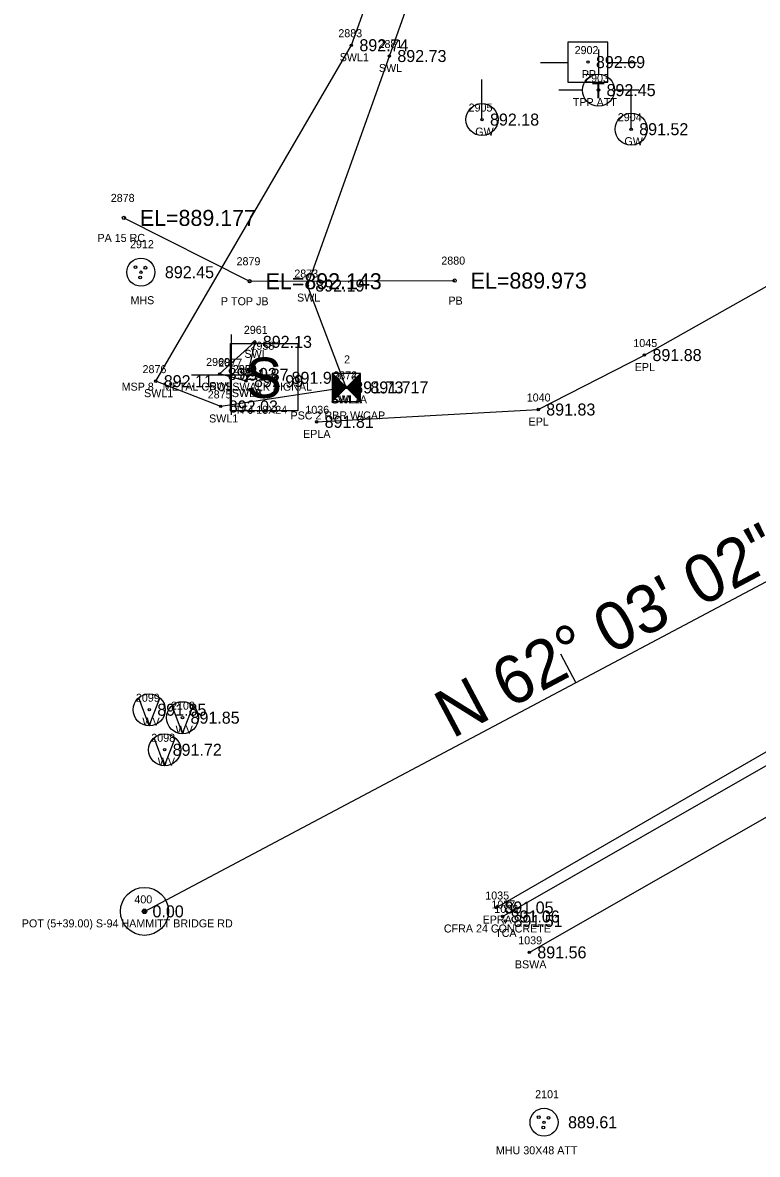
# Model space of a CAD drawing. Extents: x 1622501 to 1626664, y 1117816 to 1121579.
# Drawn here: x 1623223.8 to 1623315.6, y 1118634.5 to 1118775.8 of the extents above; entities that cross this region are included whole.
import ezdxf

# ---------------------------------------------------------------- set-up
doc = ezdxf.new("R2010")
doc.units = 0
for name, color, linetype in [('RD_EX_Conc', 7, 'Continuous'), ('RD_EX_Conc_txCode', 7, 'Continuous'), ('RD_EX_DR_Inlet', 7, 'Continuous'), ('RD_EX_DR_Pipe', 7, 'Continuous'), ('RD_EX_DR_Pipe_txCode', 7, 'Continuous'), ('RD_EX_DV_Prop_txCode', 7, 'Continuous'), ('RD_EX_Misc', 7, 'Continuous'), ('RD_EX_Misc_txCode', 7, 'Continuous'), ('RD_EX_Road', 7, 'Continuous'), ('RD_EX_Road_txCode', 7, 'Continuous'), ('RD_EX_TX_Conc_ELEV', 7, 'Continuous'), ('RD_EX_TX_Misc_ELEV', 7, 'Continuous'), ('RD_EX_TX_Road_ELEV', 7, 'Continuous'), ('RD_EX_TX_UT_ELEV', 7, 'Continuous'), ('RD_EX_UT', 7, 'Continuous'), ('RD_EX_UT_txCode', 7, 'Continuous'), ('RD_HC_Cl', 7, 'Continuous'), ('RD_HC_Data', 7, 'Continuous'), ('RD_HC_Data_Tic', 7, 'Continuous'), ('RD_HC_Survey', 7, 'Continuous'), ('RD_HC_Survey_ELEV', 7, 'Continuous'), ('RD_HC_txCode', 7, 'Continuous'), ('RD_SMD_Locator', 7, 'Continuous'), ('RD_TX_Pipe_ElevEX', 7, 'Continuous')]:
    doc.layers.add(name, color=color, linetype=linetype)

msp = doc.modelspace()

# ---------------------------------------------------------------- linework, layer by layer
at = {"layer": 'RD_EX_Conc'}
for points in [[(1623283.76, 1118664.17), (1623326.75, 1118688.79), (1623370.21, 1118712.76), (1623413.97, 1118736.47), (1623457.08, 1118761.62), (1623498.83, 1118789.05), (1623539.22, 1118818.4), (1623578.61, 1118849.25), (1623610.29, 1118876.06), (1623617.2, 1118880.67), (1623627.78, 1118883.82), (1623633.91, 1118884.57), (1623640.77, 1118884.03), (1623649.39, 1118881.53), (1623657, 1118877.66), (1623663.67, 1118871.91), (1623688.62, 1118845.06), (1623694.12, 1118836.37)], [(1623287.1, 1118659.69), (1623329.45, 1118683.88), (1623372.88, 1118707.9), (1623416.57, 1118731.52), (1623459.84, 1118756.85), (1623502.1, 1118784.62), (1623542.54, 1118813.86), (1623581.97, 1118844.89), (1623613.89, 1118871.89), (1623619.42, 1118875.42), (1623623.69, 1118876.74), (1623623.46, 1118877.27), (1623631.27, 1118878.69), (1623634.06, 1118878.85), (1623639.63, 1118878.45), (1623640.56, 1118883.37)], [(1623264.24, 1118730.25), (1623248.57, 1118727.87), (1623240.45, 1118731.03), (1623264.88, 1118772.99), (1623273.59, 1118797.21)], [(1623264.24, 1118730.25), (1623259.38, 1118742.97), (1623269.62, 1118771.64), (1623278.13, 1118795.56)], [(1623251.72, 1118731.04), (1623248.43, 1118731.93), (1623252.82, 1118735.94), (1623251.72, 1118731.04)]]:
    msp.add_lwpolyline(points, dxfattribs=at)
at = {"layer": 'RD_EX_DR_Inlet'}
for centre, radius in [((1623238.59, 1118744.64), 1.75), ((1623237.92, 1118745.27), 0.175), ((1623239.15, 1118745.2), 0.175), ((1623238.5, 1118743.98), 0.175), ((1623288.94, 1118638.47), 1.75), ((1623288.27, 1118639.1), 0.175), ((1623289.5, 1118639.03), 0.175), ((1623288.85, 1118637.81), 0.175)]:
    msp.add_circle(centre, radius, dxfattribs=at)
at = {"layer": 'RD_EX_DR_Pipe'}
msp.add_lwpolyline([(1623236.46, 1118751.42), (1623252.17, 1118743.51), (1623277.78, 1118743.59)], dxfattribs=at)
at = {"layer": 'RD_EX_DV_Prop_txCode'}
msp.add_lwpolyline([(1623249.79, 1118727.33), (1623249.79, 1118735.73), (1623258.19, 1118735.73), (1623258.19, 1118727.33)], close=True, dxfattribs=at)
at = {"layer": 'RD_EX_Misc'}
for p, q in [((1623249.9, 1118726.84), (1623249.9, 1118736.84)), ((1623244.9, 1118731.84), (1623254.9, 1118731.84))]:
    msp.add_line(p, q, dxfattribs=at)
at = {"layer": 'RD_EX_Road'}
for points in [[(1623260.54, 1118725.95), (1623288.21, 1118727.49), (1623301.48, 1118734.29), (1623344.73, 1118758.67), (1623386.19, 1118782.36), (1623428.98, 1118807.99), (1623470.08, 1118833.28), (1623514.57, 1118855.09), (1623531.48, 1118864.83), (1623546.9, 1118877), (1623552.55, 1118884.26), (1623552.91, 1118883.94), (1623553.83, 1118883.16), (1623571.54, 1118911.83), (1623572.65, 1118913.7), (1623580.36, 1118928.72), (1623584.23, 1118943.72), (1623583.03, 1118956.88), (1623577.5, 1118968.65), (1623574.75, 1118973.14), (1623569.43, 1118983.78), (1623564.78, 1119000.82), (1623565.61, 1119022.95), (1623574.2, 1119045.06)], [(1623282.99, 1118665.29), (1623326.11, 1118690.17), (1623369.47, 1118714.08), (1623413.31, 1118737.63), (1623456.35, 1118762.8), (1623498.01, 1118790.21), (1623538.41, 1118819.48), (1623577.72, 1118850.34), (1623609.41, 1118877.29), (1623616.69, 1118881.9), (1623627.61, 1118885.26), (1623634.06, 1118885.78), (1623640.82, 1118885.36), (1623649.78, 1118882.4), (1623657.44, 1118878.35), (1623664.36, 1118872.55), (1623689.27, 1118845.67), (1623694.99, 1118836.79)]]:
    msp.add_lwpolyline(points, dxfattribs=at)
at = {"layer": 'RD_EX_UT'}
for p, q in [((1623296.92, 1118773.39), (1623291.92, 1118773.39)), ((1623291.92, 1118773.39), (1623291.92, 1118768.39)), ((1623296.92, 1118768.39), (1623296.92, 1118773.39)), ((1623295.74, 1118772.45), (1623295.74, 1118769.38)), ((1623288.48, 1118770.83), (1623291.95, 1118770.83)), ((1623296.84, 1118770.83), (1623300.48, 1118770.83)), ((1623281.19, 1118763.7), (1623281.19, 1118768.7)), ((1623290.8, 1118767.4), (1623293.74, 1118767.4)), ((1623291.92, 1118768.39), (1623296.92, 1118768.39)), ((1623297.74, 1118767.4), (1623300.8, 1118767.4)), ((1623299.82, 1118762.5), (1623299.82, 1118767.5)), ((1623239.64, 1118687.99), (1623238.33, 1118691.48)), ((1623239.64, 1118687.99), (1623240.96, 1118691.44)), ((1623243.79, 1118687.01), (1623242.49, 1118690.49)), ((1623243.79, 1118687.01), (1623245.11, 1118690.46)), ((1623241.56, 1118682.99), (1623240.26, 1118686.48)), ((1623241.56, 1118682.99), (1623242.88, 1118686.44))]:
    msp.add_line(p, q, dxfattribs=at)
for centre in [(1623295.74, 1118767.38), (1623281.19, 1118763.7), (1623299.82, 1118762.5), (1623239.64, 1118689.99), (1623243.79, 1118689), (1623241.56, 1118684.99)]:
    msp.add_circle(centre, 2, dxfattribs=at)
at = {"layer": 'RD_HC_Cl'}
msp.add_line((1623239.04, 1118664.81), (1623369.72, 1118734.14), dxfattribs=at)
at = {"layer": 'RD_HC_Data'}
for radius in [3, 0.282]:
    msp.add_circle((1623239.04, 1118664.81), radius, dxfattribs=at)
at = {"layer": 'RD_HC_Data_Tic'}
msp.add_line((1623292.92, 1118693.4), (1623291.05, 1118696.93), dxfattribs=at)
at = {"layer": 'RD_HC_Survey'}
for p, q in [((1623262.5, 1118732), (1623266, 1118728.5)), ((1623266, 1118732), (1623262.5, 1118728.5)), ((1623262.52, 1118731.98), (1623262.52, 1118728.52)), ((1623262.55, 1118731.95), (1623262.55, 1118728.55)), ((1623265.95, 1118731.95), (1623265.95, 1118728.55)), ((1623265.98, 1118731.98), (1623265.98, 1118728.52)), ((1623262.57, 1118731.93), (1623262.57, 1118728.57)), ((1623262.6, 1118731.9), (1623262.6, 1118728.6)), ((1623262.62, 1118731.88), (1623262.62, 1118728.62)), ((1623262.65, 1118731.85), (1623262.65, 1118728.65)), ((1623262.67, 1118731.83), (1623262.67, 1118728.67)), ((1623262.7, 1118731.8), (1623262.7, 1118728.7)), ((1623262.72, 1118731.78), (1623262.72, 1118728.72)), ((1623262.75, 1118731.75), (1623262.75, 1118728.75)), ((1623262.77, 1118731.73), (1623262.77, 1118728.77)), ((1623262.8, 1118731.7), (1623262.8, 1118728.8)), ((1623262.82, 1118731.68), (1623262.82, 1118728.82)), ((1623262.85, 1118731.65), (1623262.85, 1118728.85)), ((1623262.87, 1118731.63), (1623262.87, 1118728.87)), ((1623262.9, 1118731.6), (1623262.9, 1118728.9)), ((1623262.92, 1118731.58), (1623262.92, 1118728.92)), ((1623262.95, 1118731.55), (1623262.95, 1118728.95)), ((1623262.97, 1118731.53), (1623262.97, 1118728.97)), ((1623262.99, 1118731.51), (1623262.99, 1118728.99)), ((1623263.02, 1118731.48), (1623263.02, 1118729.02)), ((1623263.04, 1118731.46), (1623263.04, 1118729.04)), ((1623263.07, 1118731.43), (1623263.07, 1118729.07)), ((1623263.09, 1118731.41), (1623263.09, 1118729.09)), ((1623263.12, 1118731.38), (1623263.12, 1118729.12)), ((1623263.14, 1118731.36), (1623263.14, 1118729.14)), ((1623263.17, 1118731.33), (1623263.17, 1118729.17)), ((1623263.19, 1118731.31), (1623263.19, 1118729.19)), ((1623263.22, 1118731.28), (1623263.22, 1118729.22)), ((1623263.24, 1118731.26), (1623263.24, 1118729.24)), ((1623263.27, 1118731.23), (1623263.27, 1118729.27)), ((1623263.29, 1118731.21), (1623263.29, 1118729.29)), ((1623263.32, 1118731.18), (1623263.32, 1118729.32)), ((1623263.34, 1118731.16), (1623263.34, 1118729.34)), ((1623263.37, 1118731.13), (1623263.37, 1118729.37)), ((1623263.39, 1118731.11), (1623263.39, 1118729.39)), ((1623263.42, 1118731.08), (1623263.42, 1118729.42)), ((1623263.44, 1118731.06), (1623263.44, 1118729.44)), ((1623263.47, 1118731.03), (1623263.47, 1118729.47)), ((1623263.49, 1118731.01), (1623263.49, 1118729.49)), ((1623263.51, 1118730.99), (1623263.51, 1118729.51)), ((1623263.54, 1118730.96), (1623263.54, 1118729.54)), ((1623263.56, 1118730.94), (1623263.56, 1118729.56)), ((1623263.59, 1118730.91), (1623263.59, 1118729.59)), ((1623263.61, 1118730.89), (1623263.61, 1118729.61)), ((1623263.64, 1118730.86), (1623263.64, 1118729.64)), ((1623263.66, 1118730.84), (1623263.66, 1118729.66)), ((1623263.69, 1118730.81), (1623263.69, 1118729.69)), ((1623263.71, 1118730.79), (1623263.71, 1118729.71)), ((1623263.74, 1118730.76), (1623263.74, 1118729.74)), ((1623263.76, 1118730.74), (1623263.76, 1118729.76)), ((1623263.79, 1118730.71), (1623263.79, 1118729.79)), ((1623263.81, 1118730.69), (1623263.81, 1118729.81)), ((1623263.84, 1118730.66), (1623263.84, 1118729.84)), ((1623263.86, 1118730.64), (1623263.86, 1118729.86)), ((1623263.89, 1118730.61), (1623263.89, 1118729.89)), ((1623263.91, 1118730.59), (1623263.91, 1118729.91)), ((1623263.94, 1118730.56), (1623263.94, 1118729.94)), ((1623263.96, 1118730.54), (1623263.96, 1118729.96)), ((1623264.54, 1118730.54), (1623264.54, 1118729.96)), ((1623264.56, 1118730.56), (1623264.56, 1118729.94)), ((1623264.59, 1118730.59), (1623264.59, 1118729.91)), ((1623264.61, 1118730.61), (1623264.61, 1118729.89)), ((1623264.64, 1118730.64), (1623264.64, 1118729.86)), ((1623264.66, 1118730.66), (1623264.66, 1118729.84)), ((1623264.69, 1118730.69), (1623264.69, 1118729.81)), ((1623264.71, 1118730.71), (1623264.71, 1118729.79)), ((1623264.74, 1118730.74), (1623264.74, 1118729.76)), ((1623264.76, 1118730.76), (1623264.76, 1118729.74)), ((1623264.79, 1118730.79), (1623264.79, 1118729.71)), ((1623264.81, 1118730.81), (1623264.81, 1118729.69)), ((1623264.84, 1118730.84), (1623264.84, 1118729.66)), ((1623264.86, 1118730.86), (1623264.86, 1118729.64)), ((1623264.89, 1118730.89), (1623264.89, 1118729.61)), ((1623264.91, 1118730.91), (1623264.91, 1118729.59)), ((1623264.94, 1118730.94), (1623264.94, 1118729.56)), ((1623264.96, 1118730.96), (1623264.96, 1118729.54)), ((1623264.99, 1118730.99), (1623264.99, 1118729.51)), ((1623265.01, 1118731.01), (1623265.01, 1118729.49)), ((1623265.03, 1118731.03), (1623265.03, 1118729.47)), ((1623265.06, 1118731.06), (1623265.06, 1118729.44)), ((1623265.08, 1118731.08), (1623265.08, 1118729.42)), ((1623265.11, 1118731.11), (1623265.11, 1118729.39)), ((1623265.13, 1118731.13), (1623265.13, 1118729.37)), ((1623265.16, 1118731.16), (1623265.16, 1118729.34)), ((1623265.18, 1118731.18), (1623265.18, 1118729.32)), ((1623265.21, 1118731.21), (1623265.21, 1118729.29)), ((1623265.23, 1118731.23), (1623265.23, 1118729.27)), ((1623265.26, 1118731.26), (1623265.26, 1118729.24)), ((1623265.28, 1118731.28), (1623265.28, 1118729.22)), ((1623265.31, 1118731.31), (1623265.31, 1118729.19)), ((1623265.33, 1118731.33), (1623265.33, 1118729.17)), ((1623265.36, 1118731.36), (1623265.36, 1118729.14)), ((1623265.38, 1118731.38), (1623265.38, 1118729.12)), ((1623265.41, 1118731.41), (1623265.41, 1118729.09)), ((1623265.43, 1118731.43), (1623265.43, 1118729.07)), ((1623265.46, 1118731.46), (1623265.46, 1118729.04)), ((1623265.48, 1118731.48), (1623265.48, 1118729.02)), ((1623265.51, 1118731.51), (1623265.51, 1118728.99)), ((1623265.53, 1118731.53), (1623265.53, 1118728.97)), ((1623265.55, 1118731.55), (1623265.55, 1118728.95)), ((1623265.58, 1118731.58), (1623265.58, 1118728.92)), ((1623265.6, 1118731.6), (1623265.6, 1118728.9)), ((1623265.63, 1118731.63), (1623265.63, 1118728.87)), ((1623265.65, 1118731.65), (1623265.65, 1118728.85)), ((1623265.68, 1118731.68), (1623265.68, 1118728.82)), ((1623265.7, 1118731.7), (1623265.7, 1118728.8)), ((1623265.73, 1118731.73), (1623265.73, 1118728.77)), ((1623265.75, 1118731.75), (1623265.75, 1118728.75)), ((1623265.78, 1118731.78), (1623265.78, 1118728.72)), ((1623265.8, 1118731.8), (1623265.8, 1118728.7)), ((1623265.83, 1118731.83), (1623265.83, 1118728.67)), ((1623265.85, 1118731.85), (1623265.85, 1118728.65)), ((1623265.88, 1118731.88), (1623265.88, 1118728.62)), ((1623265.9, 1118731.9), (1623265.9, 1118728.6)), ((1623265.93, 1118731.93), (1623265.93, 1118728.57)), ((1623263.98, 1118730.52), (1623263.98, 1118729.98)), ((1623264.01, 1118730.49), (1623264.01, 1118730.01)), ((1623264.03, 1118730.47), (1623264.03, 1118730.03)), ((1623264.06, 1118730.44), (1623264.06, 1118730.06)), ((1623264.08, 1118730.42), (1623264.08, 1118730.08)), ((1623264.11, 1118730.39), (1623264.11, 1118730.11)), ((1623264.13, 1118730.37), (1623264.13, 1118730.13)), ((1623264.16, 1118730.34), (1623264.16, 1118730.16)), ((1623264.18, 1118730.32), (1623264.18, 1118730.18)), ((1623264.21, 1118730.29), (1623264.21, 1118730.21)), ((1623264.23, 1118730.27), (1623264.23, 1118730.23)), ((1623264.27, 1118730.27), (1623264.27, 1118730.23)), ((1623264.29, 1118730.29), (1623264.29, 1118730.21)), ((1623264.32, 1118730.32), (1623264.32, 1118730.18)), ((1623264.34, 1118730.34), (1623264.34, 1118730.16)), ((1623264.37, 1118730.37), (1623264.37, 1118730.13)), ((1623264.39, 1118730.39), (1623264.39, 1118730.11)), ((1623264.42, 1118730.42), (1623264.42, 1118730.08)), ((1623264.44, 1118730.44), (1623264.44, 1118730.06)), ((1623264.47, 1118730.47), (1623264.47, 1118730.03)), ((1623264.49, 1118730.49), (1623264.49, 1118730.01)), ((1623264.52, 1118730.52), (1623264.52, 1118729.98))]:
    msp.add_line(p, q, dxfattribs=at)
msp.add_lwpolyline([(1623266, 1118732), (1623262.5, 1118732), (1623262.5, 1118728.5), (1623266, 1118728.5)], close=True, dxfattribs=at)
at = {"layer": 'RD_SMD_Locator'}
for centre, radius in [((1623264.88, 1118772.99), 0.15), ((1623269.62, 1118771.64), 0.15), ((1623294.42, 1118770.88), 0.15), ((1623295.74, 1118767.38), 0.15), ((1623281.19, 1118763.7), 0.15), ((1623299.82, 1118762.5), 0.15), ((1623236.46, 1118751.42), 0.2), ((1623238.59, 1118744.64), 0.15), ((1623252.17, 1118743.51), 0.2), ((1623277.78, 1118743.59), 0.2), ((1623259.38, 1118742.97), 0.15), ((1623252.82, 1118735.94), 0.15), ((1623301.48, 1118734.29), 0.15), ((1623248.43, 1118731.93), 0.15), ((1623249.9, 1118731.84), 0.15), ((1623240.45, 1118731.03), 0.15), ((1623251.72, 1118731.04), 0.15), ((1623251.72, 1118731.04), 0.15), ((1623253.91, 1118731.45), 0.15), ((1623264.24, 1118730.25), 0.15), ((1623264.24, 1118730.25), 0.15), ((1623264.25, 1118730.25), 0.15), ((1623248.57, 1118727.87), 0.15), ((1623288.21, 1118727.49), 0.15), ((1623260.54, 1118725.95), 0.15), ((1623239.64, 1118689.99), 0.15), ((1623243.79, 1118689), 0.15), ((1623241.56, 1118684.99), 0.15), ((1623239.04, 1118664.81), 0.15), ((1623282.99, 1118665.29), 0.15), ((1623283.76, 1118664.17), 0.15), ((1623284.12, 1118663.62), 0.15), ((1623287.1, 1118659.69), 0.15), ((1623288.94, 1118638.47), 0.15)]:
    msp.add_circle(centre, radius, dxfattribs=at)

# ---------------------------------------------------------------- texts
at = {"layer": 'RD_EX_Conc_txCode'}
for s, p in [('2883', (1623263.25, 1118773.99)), ('2881', (1623268.27, 1118772.64)), ('SWL1', (1623263.42, 1118770.99)), ('SWL', (1623268.32, 1118769.64)), ('2873', (1623257.75, 1118743.97)), ('SWL', (1623258.09, 1118740.97)), ('2961', (1623251.45, 1118736.94)), ('SWL', (1623251.53, 1118733.94)), ('2960', (1623246.74, 1118732.93)), ('2876', (1623238.8, 1118732.03)), ('2962', (1623250.07, 1118732.04)), ('2959', (1623250.09, 1118732.04)), ('2872', (1623262.61, 1118731.25)), ('2874', (1623262.61, 1118731.25)), ('SWL', (1623247.14, 1118729.93)), ('SWL1', (1623238.99, 1118729.03)), ('2875', (1623246.94, 1118728.87)), ('SWLA', (1623249.94, 1118729.04)), ('SWLB', (1623249.96, 1118729.04)), ('SWL1A', (1623262.3, 1118728.25)), ('SWLA', (1623262.46, 1118728.25)), ('SWL1', (1623247.11, 1118725.87)), ('1037', (1623282.37, 1118665.17)), ('1038', (1623282.73, 1118664.62)), ('CFRA 24 CONCRETE', (1623276.43, 1118662.17)), ('TCA', (1623282.83, 1118661.62)), ('1039', (1623285.72, 1118660.69)), ('BSWA', (1623285.3, 1118657.69))]:
    msp.add_text(s, height=1, dxfattribs=at).set_placement(p)
at = {"layer": 'RD_EX_DR_Pipe_txCode'}
for s, p in [('2878', (1623234.83, 1118753.42)), ('PA 15 RC', (1623233.17, 1118748.42)), ('2879', (1623250.54, 1118745.51)), ('2880', (1623276.11, 1118745.59)), ('P TOP JB', (1623248.59, 1118740.51)), ('PB', (1623277, 1118740.59))]:
    msp.add_text(s, height=1, dxfattribs=at).set_placement(p)
at = {"layer": 'RD_EX_DV_Prop_txCode'}
msp.add_text('S', height=5.04, dxfattribs=at).set_placement((1623251.71, 1118728.93))
at = {"layer": 'RD_EX_Misc_txCode'}
for s, p in [('2877', (1623248.27, 1118732.84)), ('MSP 8   METAL CROSSWALK SIGNAL', (1623236.19, 1118729.84))]:
    msp.add_text(s, height=1, dxfattribs=at).set_placement(p)
at = {"layer": 'RD_EX_Road_txCode'}
for s, p in [('1045', (1623300.09, 1118735.29)), ('EPL', (1623300.27, 1118732.29)), ('1040', (1623286.78, 1118728.49)), ('1036', (1623259.13, 1118726.95)), ('EPL', (1623287.01, 1118725.49)), ('EPLA', (1623258.85, 1118723.95)), ('1035', (1623281.6, 1118666.29)), ('EPRA', (1623281.27, 1118663.29))]:
    msp.add_text(s, height=1, dxfattribs=at).set_placement(p)
at = {"layer": 'RD_EX_TX_Conc_ELEV'}
for s, p in [('892.74', (1623265.88, 1118772.24)), ('892.73', (1623270.62, 1118770.89)), ('892.19', (1623260.38, 1118742.22)), ('892.13', (1623253.82, 1118735.19)), ('892.03', (1623249.43, 1118731.18)), ('892.11', (1623241.45, 1118730.28)), ('891.99', (1623252.72, 1118730.29)), ('891.99', (1623252.72, 1118730.29)), ('891.73', (1623265.24, 1118729.5)), ('891.73', (1623265.24, 1118729.5)), ('892.03', (1623249.57, 1118727.12)), ('891.06', (1623284.76, 1118663.42)), ('891.51', (1623285.12, 1118662.87)), ('891.56', (1623288.1, 1118658.94))]:
    msp.add_text(s, height=1.5, dxfattribs=at).set_placement(p)
at = {"layer": 'RD_EX_TX_Misc_ELEV'}
msp.add_text('891.87', height=1.5, dxfattribs=at).set_placement((1623250.9, 1118731.09))
at = {"layer": 'RD_EX_TX_Road_ELEV'}
for s, p in [('891.88', (1623302.48, 1118733.54)), ('891.83', (1623289.21, 1118726.74)), ('891.81', (1623261.54, 1118725.2)), ('891.05', (1623283.99, 1118664.54))]:
    msp.add_text(s, height=1.5, dxfattribs=at).set_placement(p)
at = {"layer": 'RD_EX_TX_UT_ELEV'}
for s, p in [('892.45', (1623296.74, 1118766.63)), ('892.18', (1623282.19, 1118762.95)), ('891.52', (1623300.82, 1118761.75)), ('892.45', (1623241.59, 1118743.89)), ('891.98', (1623257.41, 1118730.7)), ('891.85', (1623240.64, 1118689.24)), ('891.85', (1623244.79, 1118688.25)), ('891.72', (1623242.56, 1118684.24)), ('889.61', (1623291.94, 1118637.72))]:
    msp.add_text(s, height=1.5, dxfattribs=at).set_placement(p)
at = {"layer": 'RD_EX_UT'}
msp.add_text('T', height=2, dxfattribs=at).set_placement((1623294.89, 1118766.34))
at = {"layer": 'RD_EX_UT_txCode'}
for s, p in [('2902', (1623292.76, 1118771.88)), ('PP', (1623293.65, 1118768.88)), ('2903', (1623294.07, 1118768.38)), ('TPP ATT', (1623292.53, 1118765.38)), ('2905', (1623279.52, 1118764.7)), ('2904', (1623298.15, 1118763.5)), ('GW', (1623280.35, 1118761.7)), ('GW', (1623298.98, 1118760.5)), ('2912', (1623237.24, 1118747.64)), ('MHS', (1623237.29, 1118740.64)), ('2958', (1623252.28, 1118734.95)), ('TFJ 18X24', (1623250.32, 1118726.95)), ('2099', (1623237.97, 1118690.99)), ('2100', (1623242.36, 1118690)), ('WV', (1623238.78, 1118687.99)), ('2098', (1623239.89, 1118685.99)), ('WV', (1623242.93, 1118687)), ('WV', (1623240.7, 1118682.99)), ('2101', (1623287.83, 1118641.47)), ('MHU 30X48 ATT', (1623282.93, 1118634.47))]:
    msp.add_text(s, height=1, dxfattribs=at).set_placement(p)
at = {"layer": 'RD_HC_Data'}
msp.add_text('N 62%%d 03\' 02" E', height=6, rotation=27.9494, dxfattribs=at).set_placement((1623277.47, 1118686.33))
at = {"layer": 'RD_HC_Survey_ELEV'}
for s, p in [('892.69', (1623295.42, 1118770.13)), ('891.717', (1623267.25, 1118729.5)), ('0.00', (1623240.04, 1118664.06))]:
    msp.add_text(s, height=1.5, dxfattribs=at).set_placement(p)
at = {"layer": 'RD_HC_txCode'}
for s, p in [('2', (1623263.97, 1118733.25)), ('PSC 2 RBR W/CAP', (1623257.28, 1118726.25)), ('400', (1623237.78, 1118665.81)), ('POT (5+39.00) S-94 HAMMITT BRIDGE RD', (1623223.72, 1118662.81))]:
    msp.add_text(s, height=1, dxfattribs=at).set_placement(p)
at = {"layer": 'RD_TX_Pipe_ElevEX'}
for s, p in [('EL=889.177', (1623238.46, 1118750.42)), ('EL=892.143', (1623254.17, 1118742.51)), ('EL=889.973', (1623279.78, 1118742.59))]:
    msp.add_text(s, height=2, dxfattribs=at).set_placement(p)

doc.saveas('drawing.dxf')
